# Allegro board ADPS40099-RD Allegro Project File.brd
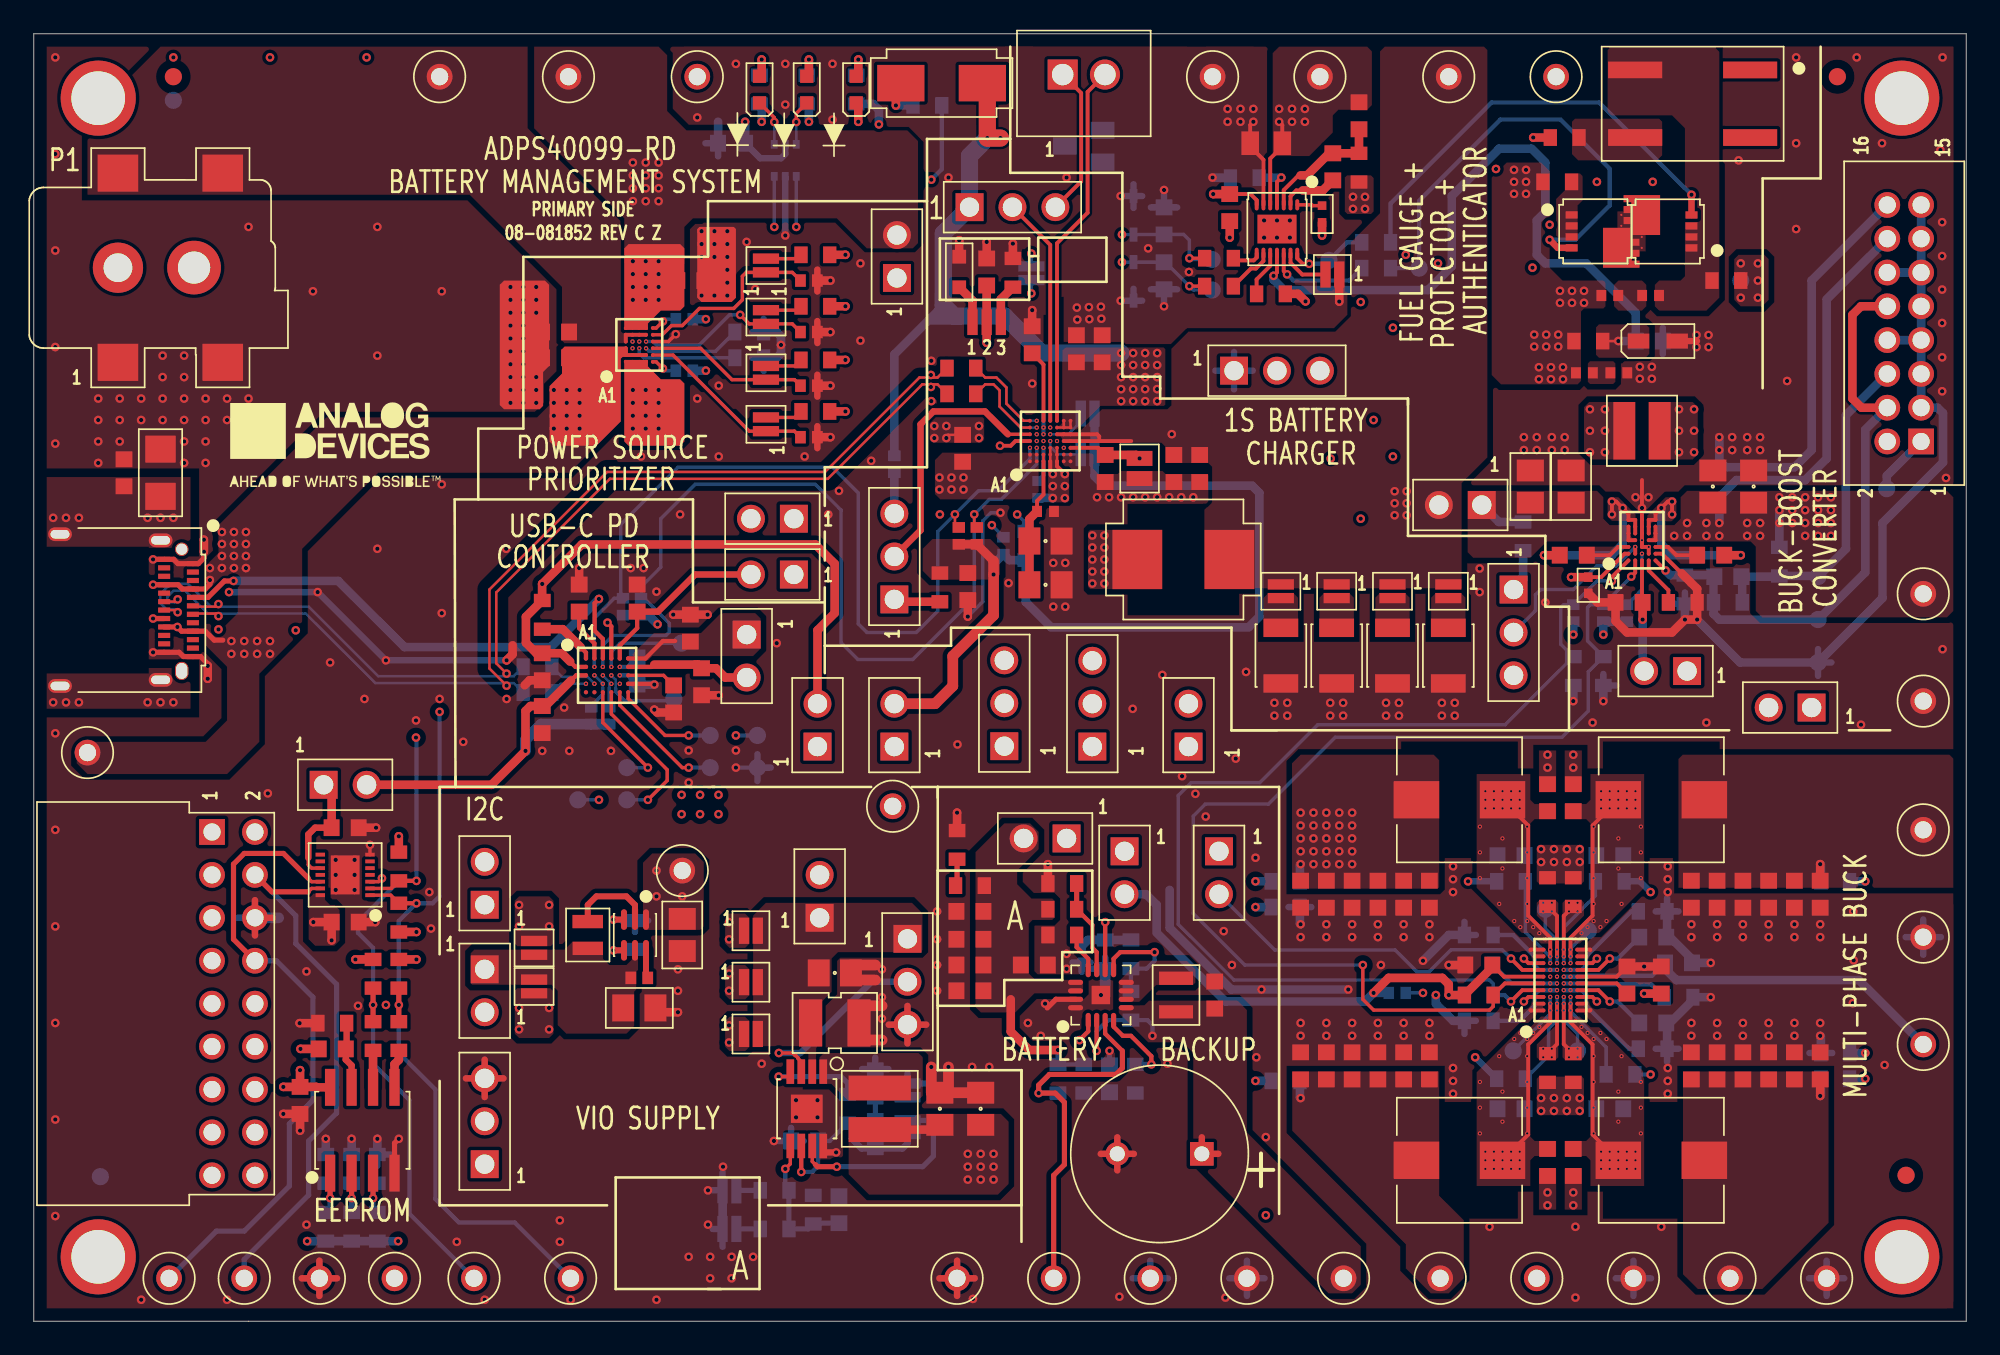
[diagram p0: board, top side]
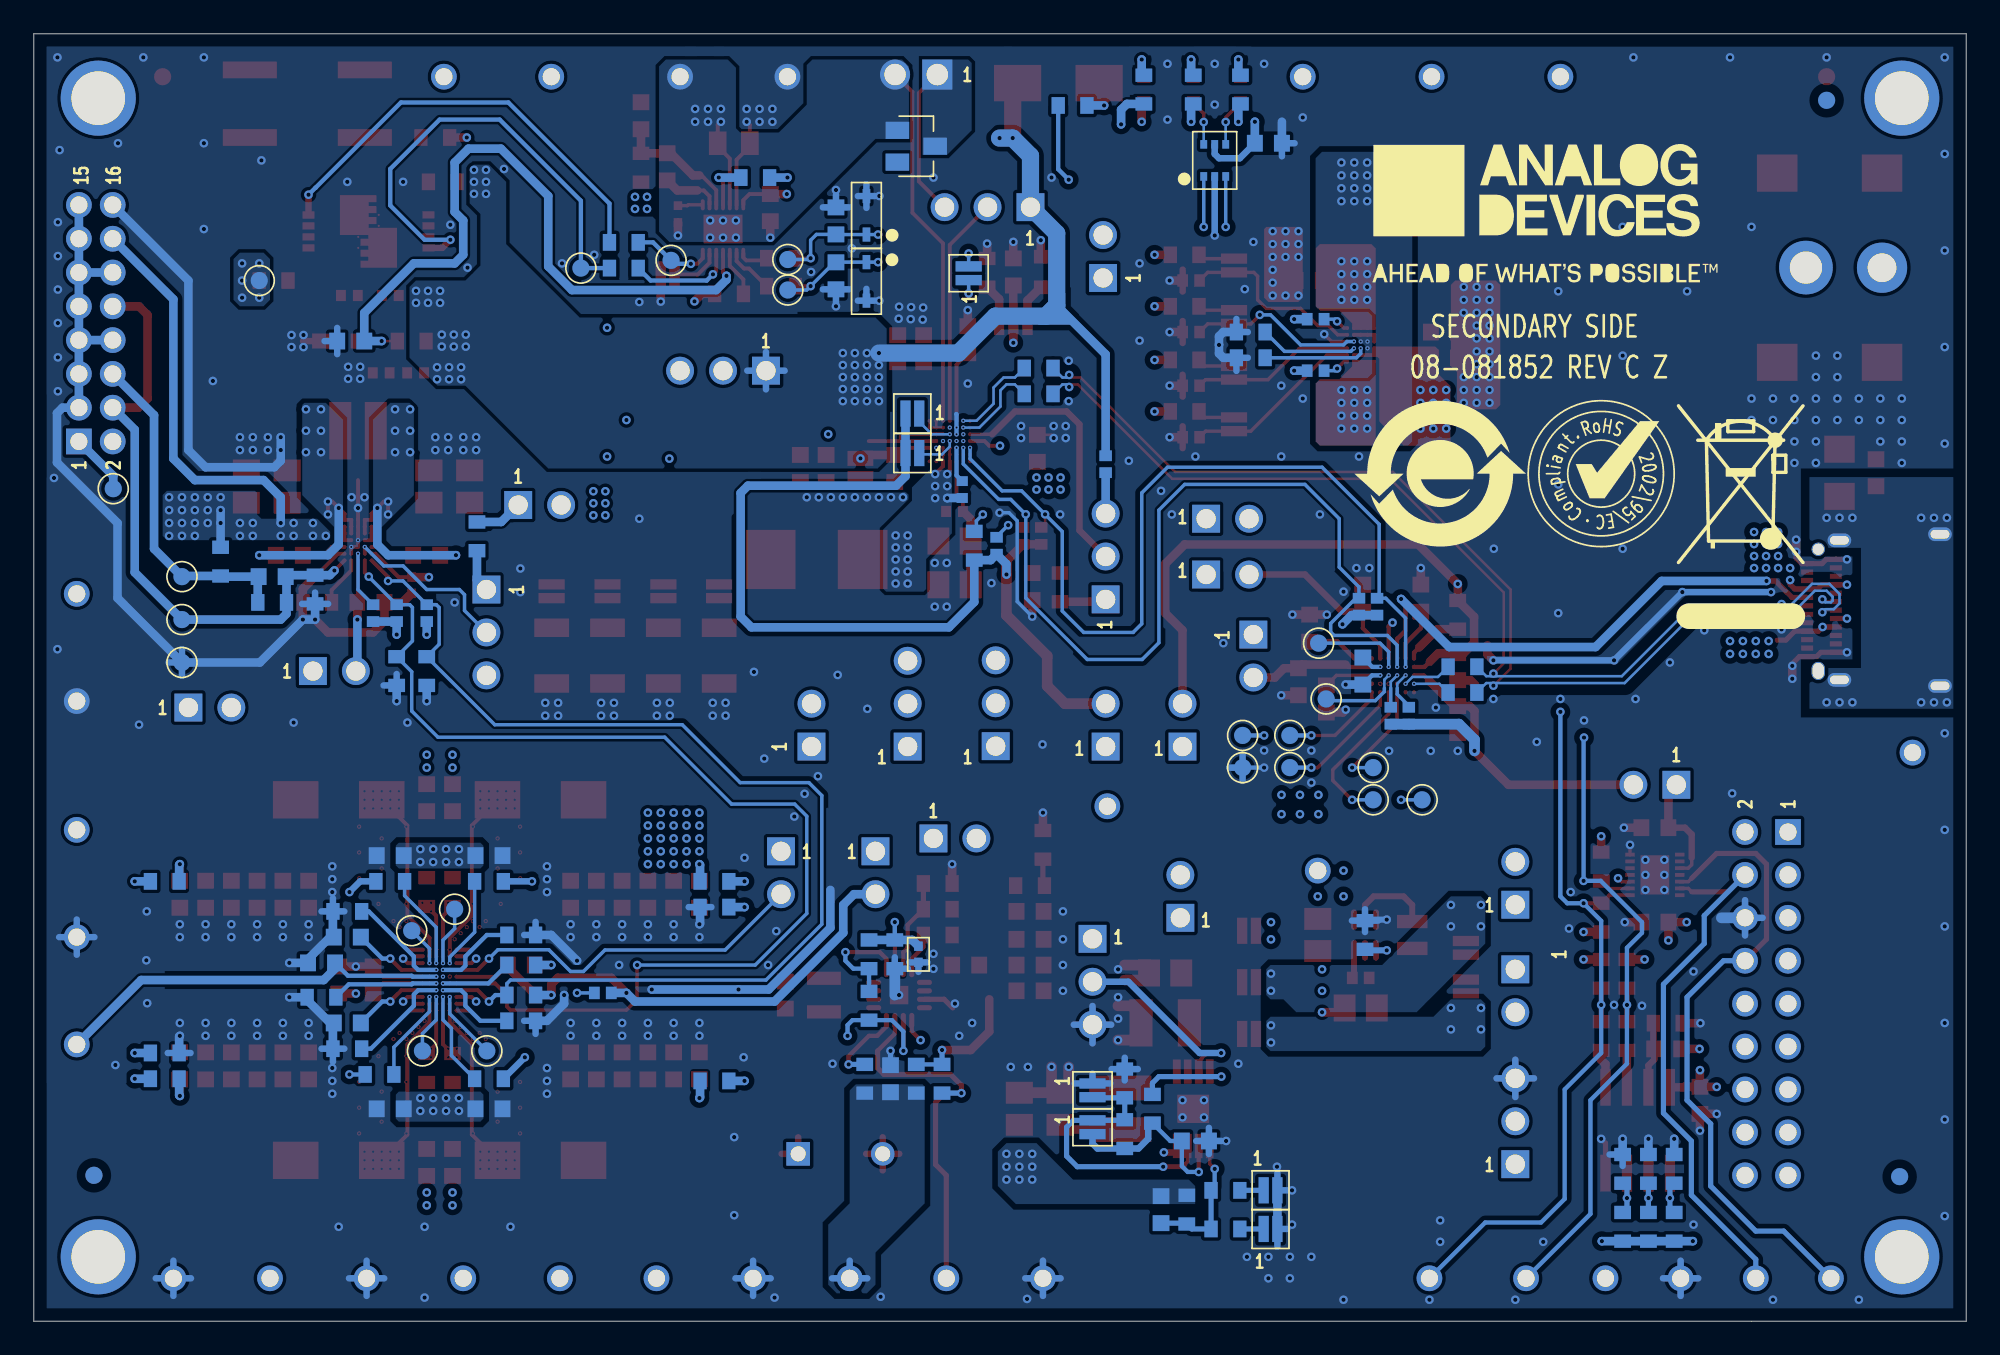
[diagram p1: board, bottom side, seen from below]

Outline 114.3 x 76.2 mm; copper layers: TOP, L2_GND, L3_SIG, L4_PWR, L5_GND, BOTTOM. Coordinates in mm from the lower left corner of the outline.
Outline path: 0,76.2 114.3,76.2 114.3,0 0,0 0,76.2

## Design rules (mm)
constraint set DEFAULT: min track width 0.152
net group USB2-IC: nets DN DP
net group USB-CN: nets DN_USBC DP_USBC
net group USB-IC1: nets DN1 DP2
net group USB_ADMAX7778X_R1: nets UNNAMED_2_ADMAX7778X_I78_DN1 UNNAMED_2_ADMAX7778X_I78_DP1
net group USB_ADMAX7778X_R2: nets UNNAMED_2_ADMAX7778X_I78_DN UNNAMED_2_ADMAX7778X_I78_DP

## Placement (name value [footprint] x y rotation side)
ALT_IN  RED  [CNKEY5001TP]  111.76 16.38 0 top
BKB  WHT  [CNKEY5001TP]  66.04 2.54 0 top
C1  0.1uF  [C0603]  5.33 50.22 270 top
C2  0.1uF  [C0603]  30.86 57.02 180 top
C3  0.1uF  [C0603]  30.86 58.55 180 top
C4  1uF  [C0603]  38.84 41.02 90 top
C5  1uF  [C0603]  30.07 38.73 270 top
C6  1uF  [C0603]  30.07 35.61 270 top
C7  1uF  [C0603]  38.86 61.59 0 top
C8  1uF  [C0603]  35.69 42.8 90 top
C9  1uF  [C0603]  35.69 38.48 270 bottom
C10  1uF  [C0603]  32.26 42.8 90 top
C11  2.2uF  [C0603]  37.85 36.83 270 top
C12  0.1uF  [C0402]  95.63 60.71 180 top
C13  1uF  [C0603]  41.28 69.72 180 bottom
C14  2.2uF  [C0603]  54.94 51.66 90 top
C15  1uF  [C0603]  55.25 43.48 270 top
C16  0.01UF  [C0603]  56.36 62.1 90 top
C17  0.22uF  [C0603]  91.06 45.34 0 top
C18  2.2uF  [C0603]  94.36 42.55 180 top
C19  1uF  [C0603]  59.05 58.09 90 top
C20  0.1uF  [C0402]  59.39 49.23 270 bottom
C21  0.22uF  [C0603]  99.19 45.34 0 top
C22  22UF  [C0603]  63.2 57.56 90 top
C23  1uF  [C0603]  63.37 50.47 270 top
C24  22uF  [C0805H60]  99.31 49.4 90 top
C25  22uF  [C0805H60]  59.84 46.18 0 top
C26  22UF  [C0603]  61.67 57.56 90 top
C27  22uF  [C0805H60]  101.73 49.4 90 top
C28  22uF  [C0805H60]  59.84 43.59 0 top
C29  0.1uF  [C0402]  59.84 47.93 0 top
C30  22UF  [C0603]  67.44 50.47 270 top
C31  22UF  [C0603]  68.96 50.47 270 top
C32  2.2uF  [C0603]  97.28 21.21 0 bottom
C33  10uF  [C0603]  87.38 12.57 180 bottom
C34  10uF  [C0603]  87.38 27.56 180 bottom
C35  10uF  [C0603]  93.22 12.57 0 bottom
C36  10uF  [C0603]  93.22 27.56 0 bottom
C37  2.2uF  [C0603]  96.27 20.19 90 top
C38  1uF  [C0603]  94.23 20.19 90 top
C39  0.1uF  [C0603]  76.84 68.33 90 top
C40  0.1uF  [C0603]  78.38 71.35 90 top
C41  0.47uF  [C0603]  70.74 65.91 270 top
C42  0.1uF  [C0603]  91.06 9.4 90 top
C43  2.2uF  [C0603]  95.76 22.73 0 bottom
C44  0.1uF  [C0603]  89.53 9.4 90 top
C45  0.1uF  [C0603]  89.53 30.99 270 top
C46  2.2uF  [C0603]  95.76 17.65 0 bottom
C47  0.1uF  [C0603]  91.06 30.99 270 top
C48  0.1uF  [C0603]  95.55 58.01 0 bottom
C49  22UF  [C0603]  98.04 15.11 90 top
C50  22UF  [C0603]  82.55 15.11 90 top
C51  22UF  [C0603]  82.55 25.27 270 top
C52  22UF  [C0603]  98.04 25.27 270 top
C53  22UF  [C0603]  99.57 15.11 90 top
C54  22UF  [C0603]  81.03 15.11 90 top
C55  22UF  [C0603]  81.03 25.27 270 top
C56  22UF  [C0603]  99.57 25.27 270 top
C57  22UF  [C0603]  101.09 15.11 90 top
C58  22UF  [C0603]  79.5 15.11 90 top
C59  22UF  [C0603]  79.5 25.27 270 top
C60  22UF  [C0603]  101.09 25.27 270 top
C61  22UF  [C0603]  102.62 15.11 90 top
C62  22UF  [C0603]  77.98 15.11 90 top
C63  22UF  [C0603]  77.98 25.27 270 top
C64  22UF  [C0603]  102.62 25.27 270 top
C65  22UF  [C0603]  104.14 15.11 90 top
C66  22UF  [C0603]  76.45 15.11 90 top
C67  22UF  [C0603]  76.45 25.27 270 top
C68  22UF  [C0603]  104.14 25.27 270 top
C69  22UF  [C0603]  105.66 15.11 90 top
C70  22UF  [C0603]  74.93 15.11 90 top
C71  22UF  [C0603]  74.93 25.27 270 top
C72  22UF  [C0603]  105.66 25.27 270 top
C73  10F  [CPLRAD197D394H472LD24]  69.09 9.91 180 top
C74  22UF  [C0603]  69.85 19.3 90 top
C75  1uF  [C0603]  85.47 21.08 180 top
C76  2200pF  [C0603]  63.63 14.35 90 bottom
C77  0.1uF  [C0402]  93.22 60.71 180 top
C78  100uF  [C1210H106]  77.06 39.4 270 top
C79  100uF  [C1210H106]  73.76 39.4 270 top
C80  100uF  [C1210H106]  83.67 39.4 270 top
C81  100uF  [C1210H106]  80.37 39.4 270 top
C82  0.1uF  [C0402]  91.72 56.13 0 top
C83  0.1uF  [C0402]  93.75 56.13 0 top
C84  10uF  [C0805H53]  88.52 49.4 90 top
C85  10uF  [C0805H53]  90.93 49.4 90 top
C86  0.47uF  [C0402H22]  91.95 43.56 270 top
C87  10pF  [C0603]  100.2 44.07 180 bottom
C88  0.47uF  [C0402H22]  61.98 21.72 270 bottom
C89  4.7uF  [C0805H60]  47.38 20.61 0 top
C90  3.3UF  [C1210H110]  47.38 17.66 0 top
C91  47uF  [C0603]  55.37 19.56 180 top
C92  47uF  [C0603]  55.37 21.08 180 top
C93  1000pF  [C0603]  66.85 65.13 90 bottom
C94  1000pF  [C0603]  66.85 61.87 270 bottom
C95  10uF  [C0805H53]  35.81 18.54 0 top
C97  22UF  [C0603]  55.37 22.61 180 top
C98  22UF  [C0603]  59.18 21.08 0 top
C101  0.1uF  [C0603]  18.41 29.21 0 top
C102  0.1uF  [C0603]  18.41 23.62 0 top
C103  1uF  [C0603]  39.5 37.85 270 top
C104  0.1uF  [C0306]  65.41 50.47 270 top
C105  1uF  [C0603]  55.37 24.26 180 top
C106  1uF  [C0603]  45.59 10.67 180 bottom
C107  22pF  [C0603]  47.62 6.6 270 bottom
C108  22uF  [C0805H60]  53.59 12.57 90 top
C109  22uF  [C0805H60]  56.01 12.57 90 top
C114  10uF  [C0805H53]  38.35 22.86 270 top
C116  0.1uF  [C0603]  15.75 13.07 270 top
C117  0.1uF  [C0603]  17.65 16.12 0 top
CSN  WHT  [CNKEY5001TP]  69.72 73.66 0 top
CSP  WHT  [CNKEY5001TP]  76.07 73.66 0 top
D1  BZX84-A5V6,215  [SOT23]  62.1 69.55 270 bottom
D2  ZLLS400TA  [SOD323]  96.06 58.01 0 top
D3  BZX84J-B5V6,115  [SOD323F]  65.05 65.46 90 bottom
D4  BZX84J-B5V6,115  [SOD323F]  65.05 61.54 270 bottom
DS1  HSMS-C191  [LED0603-2]  45.72 72.9 90 top
DS2  HSMS-C191  [LED0603-2]  42.93 72.9 90 top
DS3  HSMS-C191  [LED0603-2]  48.64 72.9 90 top
E1  120OHM  [L1206-3]  7.49 50.22 90 top
GND1  BLK  [CNKEY5001TP]  106.05 2.54 0 top
GND2  BLK  [CNKEY5001TP]  94.62 2.54 0 top
GND3  BLK  [CNKEY5001TP]  71.75 2.54 0 top
GND4  BLK  [CNKEY5001TP]  111.76 22.73 0 top
GND5  BLK  [CNKEY5001TP]  111.76 36.7 0 top
GND6  BLK  [CNKEY5001TP]  16.89 2.54 0 top
GNDC  BLK  [CNKEY5001TP]  54.61 2.54 0 top
IN+  TESTPAD  [TPSMC40]  105.54 41.53 180 bottom
IN_U3  RED  [CNKEY5001TP]  90.04 73.66 0 top
JP1  3PIN_SOLDER_JUMPER  [JPRSLD03]  56.36 59.13 0 top
L1  1.5UH  [LSMSQ118H47_WE]  95.12 52.71 180 top
L2  1UH  [LSMSQ260H118]  68 45.09 0 top
L3  1.5UH  [LSMSQ272H157]  96.27 9.53 0 top
L4  1.5UH  [LSMSQ272H157]  84.33 9.53 180 top
L5  1.5UH  [LSMSQ272H157]  84.33 30.86 180 top
L6  1.5UH  [LSMSQ272H157]  96.27 30.86 0 top
L7  0.47UH  [L1008H47]  67.56 19.3 90 top
L8  4.7uH  [LSMSQ157H83]  50.04 12.57 270 top
L9  2.2UH  [L0806_DFE]  32.77 22.86 90 top
M1  12401598E4#2A  [M12401598E4_2A]  4.41 42.09 270 top
NOREF  -  []  114.3 0 90 top
NOREF#2  -  []  0 0 0 top
NOREF#3  -  [unnamed#2]  110.49 72.39 0 top
NOREF#4  -  []  110.49 3.81 0 top
NOREF#5  -  []  0 76.2 0 top
NOREF#6  -  []  0 76.2 270 top
NOREF#7  -  []  3.81 3.81 0 top
NOREF#8  -  []  17.53 51.84 0 top
NOREF#9  -  []  114.3 0 90 top
NOREF#10  -  []  114.3 76.2 180 top
NOREF#11  -  [unnamed#2]  8.26 73.66 0 top
NOREF#12  -  []  3.81 3.81 0 top
NOREF#13  -  [unnamed#2]  3.81 72.39 0 top
NOREF#14  -  []  0 76.2 0 top
NOREF#15  -  []  193.8 133.99 0 top
NOREF#16  -  [unnamed#2]  3.81 3.81 0 top
NOREF#17  -  []  -209.55 -146.05 0 top
NOREF#18  -  [unnamed#2]  110.49 3.81 0 top
NOREF#19  -  []  0 0 0 top
NOREF#20  -  [unnamed#2]  106.68 73.66 90 top
NOREF#21  -  []  -209.55 -146.05 0 top
NOREF#22  -  []  -209.55 -146.05 0 top
NOREF#23  -  []  114.3 0 0 top
NOREF#24  -  []  171.45 307.59 0 top
NOREF#25  -  []  0 0 0 top
NOREF#26  -  [unnamed#2]  110.74 8.64 0 top
NOREF#27  -  []  56.87 95.63 0 top
NOREF#28  -  [unnamed#2]  8.26 72.26 180 bottom
NOREF#29  -  []  25.48 65.56 180 bottom
NOREF#30  -  []  31.11 50.16 180 bottom
NOREF#31  -  [unnamed#2]  110.74 8.64 180 bottom
NOREF#32  -  []  21.59 50.16 180 bottom
NOREF#33  -  [unnamed#2]  3.94 8.56 270 bottom
NOREF#34  -  []  4.06 57.86 180 bottom
OUT1  RED  [CNKEY5001TP]  100.33 2.54 0 top
OUT2  RED  [CNKEY5001TP]  83.19 2.54 0 top
OUT3  RED  [CNKEY5001TP]  88.9 2.54 0 top
OUT4  RED  [CNKEY5001TP]  111.76 29.08 180 top
OUT5  RED  [CNKEY5001TP]  111.76 43.05 0 top
OUT+  TESTPAD  [TPSMC40]  105.54 44.07 180 bottom
OUT-  TESTPAD  [TPSMC40]  105.54 38.99 180 bottom
P1  KLDX-SMT2-0202-ATR-1  [CNKYCONKLDX-SMT2-0202-ATR-1]  7.24 62.36 0 top
P2  B2B-XH-A(LF)(SN)  [CNHDR1X2H276]  60.86 73.79 0 top
P3  HTSW-102-07-T-S  [CNTHMHDR1X2L200W98H343]  70.1 27.81 270 top
P4  HTSW-102-07-T-S  [CNTHMHDR1X2L200W98H343]  105.16 36.32 180 top
P5  -  [JPSLD02]  43.31 59.44 270 top
P6  -  [JPSLD02]  43.31 56.13 270 top
P7  -  [JPSLD02]  43.31 53.09 90 top
P8  -  [JPSLD02]  43.31 62.48 90 top
P9  -  [JPSLD02]  76.81 61.95 180 top
P10  HTSW-102-07-T-S  [CNTHMHDR1X2L200W98H343]  26.67 24.65 90 top
P11  HTSW-103-07-T-S  [CNTHMHDR1X3L300W98H343]  57.4 34.04 90 top
P12  HTSW-102-07-T-S  [CNTHMHDR1X2L200W98H343]  46.48 23.88 90 top
P13  HTSW-102-07-T-S  [CNTHMHDR1X2L200W98H343]  42.16 40.64 270 top
P14  087831-1620  [CNTHMHDR2X8L734W248H260]  111.63 52.07 90 top
P15  PPPC092LJBN-RC  [CNTHFHDRRA2X9L920W335H208]  10.54 28.96 270 top
P16  HTSW-103-07-T-S  [CNTHMHDR1X3L300W98H343]  50.9 42.72 90 top
P17  HTSW-103-07-T-S  [CNTHMHDR1X3L300W98H343]  87.53 43.31 270 top
P18  HTSW-102-07-T-S  [CNTHMHDR1X2L200W98H343]  97.79 38.48 180 top
P19  HTSW-102-07-T-S  [CNTHMHDR1X2L200W98H343]  61.09 28.57 180 top
P20  HTSW-103-07-T-S  [CNTHMHDR1X3L300W98H343]  55.35 65.94 0 top
P21  HTSW-102-07-T-S  [CNTHMHDR1X2L200W98H343]  44.96 47.5 180 top
P22  HTSW-102-07-T-S  [CNTHMHDR1X2L200W98H343]  46.36 34.01 90 top
P23  HTSW-102-07-T-S  [CNTHMHDR1X2L200W98H343]  17.14 31.75 0 top
P24  HTSW-102-07-T-S  [CNTHMHDR1X2L200W98H343]  68.3 34.01 90 top
P25  -  [JPSLD02]  62.33 51.38 0 bottom
P26  HTSW-102-07-T-S  [CNTHMHDR1X2L200W98H343]  50.9 34.01 90 top
P27  HTSW-103-07-T-S  [CNTHMHDR1X3L300W98H343]  62.61 34.01 90 top
P28  -  [JPSLD02]  41.15 5.46 180 bottom
P29  HTSW-102-07-T-S  [CNTHMHDR1X2L200W98H343]  64.52 27.81 270 top
P30  HTSW-102-07-T-S  [CNTHMHDR1X2L200W98H343]  51.05 61.75 90 top
P31  -  [JPSLD02]  77.06 43.21 270 top
P32  -  [JPSLD02]  73.76 43.21 270 top
P33  -  [JPSLD02]  83.67 43.21 270 top
P34  -  [JPSLD02]  80.37 43.21 270 top
P35  HTSW-102-07-T-S  [CNTHMHDR1X2L200W98H343]  85.65 48.31 180 top
P36  -  [JPSLD02]  62.33 53.72 0 bottom
P37  -  [JPSLD02]  59 62.03 90 bottom
P38  -  [JPSLD02]  41.15 7.75 180 bottom
P39  HTSW-103-07-T-S  [CNTHMHDR1X3L300W98H343]  51.68 22.63 270 top
P40  HTSW-103-07-T-S  [CNTHMHDR1X3L300W98H343]  70.99 56.26 0 top
P41  -  [JPSLD02]  51.68 11.48 270 bottom
P42  -  [JPSLD02]  51.68 13.67 270 bottom
P43  -  [JPSLD02]  42.42 17 0 top
P44  -  [JPSLD02]  42.42 20.07 0 top
P45  -  [JPSLD02]  42.42 23.11 0 top
P46  HTSW-102-07-T-S  [CNTHMHDR1X2L200W98H343]  26.67 20.83 270 top
P47  HTSW-103-07-T-S  [CNTHMHDR1X3L300W98H343]  26.67 9.29 90 top
P48  -  [JPSLD02]  29.59 19.81 90 top
P49  -  [JPSLD02]  29.59 22.1 270 top
P50  HTSW-102-07-T-S  [CNTHMHDR1X2L200W98H343]  44.96 44.2 180 top
PP_OUT  RED  [CNKEY5001TP]  31.62 73.66 180 top
Q1  FDMC0310AS-F127  [DFN8_3_3X3_3_511DH]  96.65 64.5 90 top
Q2  FDMC0310AS-F127  [DFN8_3_3X3_3_511DH]  92.36 64.51 270 top
R1  0  [R0603]  42.32 57.02 0 bottom
R2  0  [R0603]  42.32 58.55 0 bottom
R3  1K  [R0603]  46.23 60.07 180 top
R4  1K  [R0603]  46.23 56.9 180 top
R5  2.2K  [R0402]  34.04 35.84 90 bottom
R6  100K  [R0402]  45.85 58.55 180 top
R7  100K  [R0402]  45.85 55.37 180 top
R8  2.2K  [R0402]  32.97 35.84 90 bottom
R9  100K  [R0402]  38.48 56.26 0 bottom
R10  100K  [R0402]  38.48 59.31 0 bottom
R11  100K  [R0402]  45.85 52.32 0 top
R12  100K  [R0402]  45.85 61.59 0 top
R13  1K  [R0603]  46.23 53.85 0 top
R14  1K  [R0603]  46.23 63.12 0 top
R15  10K  [R0603]  93.85 14.61 0 bottom
R16  0  [R0603]  29.79 37.21 0 bottom
R17  0  [R0603]  29.79 38.73 0 bottom
R18  150  [R0603]  45.72 72.9 90 bottom
R19  150  [R0603]  42.93 72.9 90 bottom
R20  10K  [R0603]  57.91 62.05 90 top
R21  2.2K  [R0402]  55.78 46.48 90 top
R22  2.2K  [R0402]  54.71 46.48 90 top
R23  1K  [R0603]  52.86 71.96 0 bottom
R24  0  [R0603]  58.67 45.9 270 bottom
R25  2.2K  [R0402]  34.85 42.29 90 bottom
R26  0  [R0603]  54.86 54.89 0 top
R27  15K  [R0402]  94.23 41.91 90 bottom
R28  100K  [R0402]  57.35 45.9 90 bottom
R29  150  [R0603]  48.64 72.9 90 bottom
R30  10  [R0603]  78.38 68.28 90 top
R31  10K  [R0402H26]  76.2 65.53 90 top
R32  0  [R0603]  71.63 67.69 180 bottom
R33  0.01  [R0805]  72.9 69.72 180 top
R34  200  [R0603]  73.18 60.81 0 top
R35  1K  [R0603]  79.4 63.86 0 bottom
R36  1K  [R0603]  79.4 62.33 0 bottom
R37  0  [R0603]  70.1 61.26 0 top
R38  0  [R0603]  106.55 14.35 0 bottom
R39  0  [R0603]  106.55 15.88 0 bottom
R40  0  [R0603]  74.04 14.22 180 bottom
R41  0  [R0603]  74.04 26.04 180 bottom
R42  0  [R0603]  74.04 24.51 180 bottom
R43  0  [R0603]  106.55 26.04 0 bottom
R44  0  [R0603]  100.12 61.59 0 top
R45  0  [R0603]  35.56 22.86 90 bottom
R46  64.9K  [R0603]  95.76 16.13 0 bottom
R47  10K  [R0603]  87.38 14.35 180 bottom
R48  30.9K  [R0603]  85.47 17.78 180 bottom
R49  0  [R0603]  97.28 19.18 180 bottom
R50  8.06K  [R0603]  85.47 22.86 180 bottom
R51  1.8MEG  [R0603]  64.9 18.67 90 bottom
R52  402K  [R0603]  64.9 21.72 90 bottom
R53  499K  [R0603]  63.37 21.72 270 bottom
R54  0  [R0603]  85.47 21.08 0 bottom
R55  1.62K  [R0603]  95.76 24.26 0 bottom
R56  1.5K  [R0603]  85.47 19.3 0 bottom
R57  33K  [R0603]  60.83 22.86 180 top
R58  2.2K  [R0402]  35.92 42.29 90 bottom
R59  1.5K  [R0603]  85.47 19.3 180 top
R60  100K  [R0402]  80.64 19.43 180 bottom
R61  0  [R0603]  20.32 5.59 90 bottom
R62  100K  [R0603]  20.32 9.02 90 bottom
R63  200K  [R0603]  30.07 41.81 90 top
R64  4.7K  [R0603]  53.59 43.43 270 top
R65  100K  [R0402]  50.9 50.72 270 bottom
R66  1K  [R0603]  90.55 70.06 180 top
R67  1K  [R0603]  91.95 58.01 0 top
R68  0  [R0603]  91.06 14.99 270 top
R69  0  [R0603]  55.37 25.78 180 top
R70  10K  [R0603]  87.38 26.04 180 bottom
R71  1.8MEG  [R0603]  60.83 24.38 0 top
R72  1.21M  [R0603]  60.83 25.91 180 top
R73  0  [R0603]  89.53 14.99 270 top
R74  0  [R0603]  89.53 25.4 90 top
R75  0  [R0603]  91.06 25.4 90 top
R76  510K  [R0603]  88.09 46.46 270 bottom
R77  0  [R0603]  97.54 42.55 0 top
R78  2.2K  [R0402]  91.06 41.91 90 bottom
R79  0  [R0603]  91.06 38.48 270 bottom
R80  2.2K  [R0402]  92.84 41.91 90 bottom
R81  0  [R0603]  92.84 38.48 270 bottom
R82  0  [R0603]  103.25 44.96 90 bottom
R83  0  [R0603]  100.2 42.55 180 bottom
R84  20K  [R0603]  97.66 43.31 270 bottom
R85  10K  [R0603]  93.22 26.04 0 bottom
R86  0  [R0603]  70.1 62.92 0 top
R87  0  [R0603]  90.11 67.44 0 top
R88  2.2K  [R0603]  21.59 26.91 270 top
R89  2.2K  [R0603]  21.59 23.89 90 top
R90  0  [R0603]  54.86 56.41 0 top
R91  309K  [R0603]  43.82 5.46 180 bottom
R92  84.5K  [R0603]  43.82 7.75 180 bottom
R93  0  [R0603]  54.86 54.89 180 bottom
R94  0  [R0603]  54.86 56.41 180 bottom
R95  20K  [R0603]  65.15 14.35 270 bottom
R96  1MEG  [R0603]  62.1 14.35 270 bottom
R97  1MEG  [R0603]  60.58 14.35 270 bottom
R98  100  [R0603]  54.61 28.19 90 top
R99  100K  [R0603]  48.13 12.57 270 bottom
R100  100K  [R0603]  49.77 11.07 90 bottom
R101  100K  [R0603]  49.77 14.07 90 bottom
R102  619K  [R0603]  46.1 6.6 270 bottom
R103  33M  [R0402]  35.81 20.32 0 top
R109  100K  [R0603]  18.8 5.59 90 bottom
R110  0  [R0603]  18.8 9.02 90 bottom
R111  0  [R0603]  17.27 5.59 90 bottom
R112  100K  [R0603]  17.27 9.02 90 bottom
R113  0  [R0603]  20.07 16.88 90 top
R114  0  [R0603]  21.59 16.88 90 top
R115  10K  [R0603]  20.07 20.56 270 top
R116  10K  [R0603]  21.59 20.56 270 top
R117  0  [R0603]  17.65 17.64 180 top
RDY  WHT  [CNKEY5001TP]  60.33 2.54 0 top
RT1  10K  [R0603H35]  54.74 62.1 90 top
S1  EVQ-Q2K03W  [SWPANASONIC_EVQ]  98.12 72.06 180 top
S2  TL3302AF130QJ  [SWSML236W138H205]  53.7 73.28 0 top
SCL  WHT  [CNKEY5001TP]  26.04 2.54 0 top
SCL_EXT  WHT  [CNKEY5001TP]  8 2.54 0 top
SDA  WHT  [CNKEY5001TP]  31.75 2.54 0 top
SDA_EXT  WHT  [CNKEY5001TP]  12.45 2.54 0 top
TP1  TESTPAD  [TPSMC40]  40.01 34.67 180 bottom
TP6  TESTPAD  [TPSMC40]  76.61 62.79 180 bottom
TP9  TESTPAD  [TPSMC40]  38.3 40.13 180 bottom
TP10  TESTPAD  [TPSMC40]  40.01 32.77 180 bottom
TP11  TESTPAD  [TPSMC40]  42.8 34.67 180 bottom
TP12  TESTPAD  [TPSMC40]  35.08 30.86 180 bottom
TP13  TESTPAD  [TPSMC40]  35.08 32.77 180 bottom
TP17  TESTPAD  [TPSMC40]  32.18 30.86 180 bottom
TP18  TESTPAD  [TPSMC40]  37.86 36.83 180 bottom
TP19  TESTPAD  [TPSMC40]  42.8 32.77 180 bottom
TP20  TESTPAD  [TPSMC40]  69.7 62.84 180 bottom
TP21  TESTPAD  [TPSMC40]  109.6 49.28 180 bottom
TP23  TESTPAD  [TPSMC40]  91.31 16 180 bottom
TP25  TESTPAD  [TPSMC40]  87.5 16 180 bottom
TP27  TESTPAD  [TPSMC40]  89.41 24.38 180 bottom
TP29  TESTPAD  [TPSMC40]  91.95 23.11 180 bottom
TP30  TESTPAD  [TPSMC40]  100.97 61.59 180 bottom
TP31  TESTPAD  [TPSMC40]  69.7 61.04 180 bottom
TP32  TESTPAD  [TPSMC40]  81.94 62.33 180 bottom
U1  MAX14727EWV+  [WLP30_21-0762]  35.81 57.79 90 top
U2  MAX77958EWV+  [WLCSP30H27]  33.91 38.23 270 top
U3  MAX77857BEWB+  [WLCSP35H27]  95.12 46.23 0 top
U4  MAX17300G+  [DFN14_3X3_PAD2_3X1_7]  73.53 64.64 180 top
U5  MAX38889AATE+  [QFN16_3X3_PAD1_1X1_1]  63.12 19.3 0 top
U6  MAX77542BAWU+T  [WLCSP60H27]  90.3 20.19 0 top
U7  NC7WZ07P6X  [SC70]  44.45 68.71 180 bottom
U8  MAX77786EWJ+  [WLP49_2_958X2_958]  60.12 52.1 90 top
U9  LTC3621IMS8E#PBF  [MSOP8_PAD1_88X1_68]  45.72 12.57 180 top
U10  MAX17224ALT+  [DFN6_2X2]  35.56 22.86 180 top
U13  MAX14611ETD+  [TDFN14_PAD2_3X1_7]  18.41 26.42 90 top
U14  24AA32A-I/SN  [SO8]  19.43 11.3 0 top
UNK1V8_VIO  RED  [CNKEY5001TP]  50.8 30.48 0 top
UNK5V0_VIO  RED  [CNKEY5001TP]  38.35 26.67 0 top
UNK12V0  RED  [CNKEY5001TP]  24 73.66 0 top
VBUS  RED  [CNKEY5001TP]  3.17 33.66 0 top
VCAP  RED  [CNKEY5001TP]  77.47 2.54 0 top
VCC_EXT  RED  [CNKEY5001TP]  21.34 2.54 0 top
VIO  RED  [CNKEY5001TP]  39.24 73.66 180 top
VSYS  RED  [CNKEY5001TP]  83.69 73.66 0 top

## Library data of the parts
ALT_IN IN_U3 OUT1-OUT5 PP_OUT UNK1V8_VIO UNK5V0_VIO UNK12V0 VBUS VCAP VCC_EXT VIO VSYS = CNTP1P: Tolerance: N/A; User Part Number: UPN; alternate symbols: (CNKEY5001TP); part number: CNTP1P_TH-RED,E016323,CNKEY5001TP; tolerance: N/A
BKB CSN CSP RDY SCL SCL_EXT SDA SDA_EXT = CNTP1P: Tolerance: N/A; User Part Number: UPN; alternate symbols: (CNKEY5001TP); part number: CNTP1P_TH-WHT,E006153,CNKEY5001TP; tolerance: N/A
C1-C3 C39 C40 C42 C44 C45 C47 C48 C101 C102 C116 C117 = CAP: User Part Number: UPN; Tolerance: 10; alternate symbols: (C0603); part number: CAP_SM-0.1UF,25V,10,E013746,C0603; tolerance: 10
C4-C10 C13 C15 C19 C23 C38 C75 C103 C105 C106 = CAP: User Part Number: UPN; Tolerance: 10; alternate symbols: (C0603); part number: CAP_SM-1UF,50V,10,E032711,C0603; tolerance: 10
C11 C14 C18 C32 C37 C43 C46 = CAP: User Part Number: UPN; Tolerance: 10; alternate symbols: (C0603); part number: CAP_SM-2.2UF,25V,10,E031885,C0603; tolerance: 10
C12 C77 C82 C83 = CAP: User Part Number: UPN; Tolerance: 10; alternate symbols: (C0402); part number: CAP_SM-0.1UF,25V,10,E025798,C0402; tolerance: 10
C16 = CAP: User Part Number: UPN; Tolerance: 5; alternate symbols: (C0603); part number: CAP_SM-0.01UF,50V,5,E054559,C0603; tolerance: 5
C17 C21 = CAP: User Part Number: UPN; Tolerance: 10; alternate symbols: (C0603); part number: CAP_SM-0.22UF,50V,10,E015565,C0603; tolerance: 10
C20 C29 = CAP: User Part Number: UPN; Tolerance: 10; alternate symbols: (C0402); part number: CAP_SM-0.1UF,50V,10,E028943,C0402; tolerance: 10
C22 C26 C30 C31 C49-C72 C74 C97 C98 = CAP: User Part Number: UPN; Tolerance: 20; alternate symbols: (C0603); part number: CAP_SM-22UF,10V,20,E059718,C0603; tolerance: 20
C24 C25 C27 C28 C108 C109 = CAP: Tolerance: 20; User Part Number: UPN; alternate symbols: (C0805H60); part number: CAP_SM-22UF,35V,20,E025497,C0805H60; tolerance: 20
C33-C36 = CAP: User Part Number: UPN; Tolerance: 10; alternate symbols: (C0603); part number: CAP_SM-10UF,10V,10,E020723,C0603; tolerance: 10
C41 = CAP: User Part Number: UPN; Tolerance: 10; alternate symbols: (C0603); part number: CAP_SM-0.47UF,35V,10,E019601,C0603; tolerance: 10
C73 = CAPP: User Part Number: UPN; Tolerance: -10%,+30; alternate symbols: (CPLRAD197D394H472LD24); part number: CAPP_TH-10F,3V,-10%,+30,E065865,CPLRAD197D394H472LD24; tolerance: -10%,+30
C76 = CAP: User Part Number: UPN; Tolerance: 5; alternate symbols: (C0603); part number: CAP_SM-2200PF,50V,5,E012265,C0603; tolerance: 5
C78-C81 = CAP: Tolerance: 20; User Part Number: UPN; alternate symbols: (C1210H106); part number: CAP_SM-100UF,16V,20,E029581,C1210H106; tolerance: 20
C84 C85 C95 C114 = CAP: Tolerance: 10; User Part Number: UPN; alternate symbols: (C0805H53); part number: CAP_SM-10UF,25V,10,E029697,C0805H53; tolerance: 10
C86 C88 = CAP: Tolerance: 10; User Part Number: UPN; alternate symbols: (C0402H22); part number: CAP_SM-0.47UF,6.3V,10,E030257,C0402H22; tolerance: 10
C87 = CAP: User Part Number: UPN; Tolerance: 5; alternate symbols: (C0603); part number: CAP_SM-10PF,250V,5,E017800,C0603; tolerance: 5
C89 = CAP: Tolerance: 10; User Part Number: UPN; alternate symbols: (C0805H60); part number: CAP_SM-4.7UF,25V,10,E024738,C0805H60; tolerance: 10
C90 = CAP: Tolerance: 20; User Part Number: UPN; alternate symbols: (C1210H110); part number: CAP_SM-3.3UF,50V,20,E042926,C1210H110; tolerance: 20
C91 C92 = CAP: User Part Number: UPN; Tolerance: 20; alternate symbols: (C0603); part number: CAP_SM-47UF,6.3V,20,E032368,C0603; tolerance: 20
C93 C94 = CAP: User Part Number: UPN; Tolerance: 5; alternate symbols: (C0603); part number: CAP_SM-1000PF,25V,5,E035602,C0603; tolerance: 5
C104 = CAP: Tolerance: 10; User Part Number: UPN; alternate symbols: (C0306); part number: CAP_SM-0.1UF,10V,10,E000379,C0306; tolerance: 10
C107 = CAP: User Part Number: UPN; Tolerance: 5; alternate symbols: (C0603); part number: CAP_SM-22PF,50V,5,E000411,C0603; tolerance: 5
D1 = DIOZNR3P_V3: User Part Number: UPN; Tolerance: 1; alternate symbols: (SOT23); part number: DIOZNR3P_V3_SM-BZX84-A5V6,215,5.6V,1,E045330,SOT23; tolerance: 1
D2 = DIOSCHOTTKY: Tolerance: N/A; User Part Number: UPN; alternate symbols: (SOD323); part number: DIOSCHOTTKY_SM-ZLLS400TA,40V,N/A,E032795,SOD323; tolerance: N/A
D3 D4 = DIOZNR: Tolerance: 2; User Part Number: UPN; alternate symbols: (SOD323F); part number: DIOZNR_SM-BZX84J-B5V6,115,5.6V,2,E059375,SOD323F; tolerance: 2
DS1-DS3 = DIOLED: Tolerance: N/A; User Part Number: UPN; alternate symbols: (LED0603-2); part number: DIOLED_SM-HSMS-C191,2.1V,N/A,E029018,LED0603-2; tolerance: N/A
E1 = FERRITE: Tolerance: 25; User Part Number: UPN; alternate symbols: (L1206-3); part number: FERRITE_SM-120OHM,25,E021151,L1206-3; tolerance: 25
GND1-GND6 GNDC = CNTP1P: Tolerance: N/A; User Part Number: UPN; alternate symbols: (CNKEY5001TP); part number: CNTP1P_TH-BLK,E005347,CNKEY5001TP; tolerance: N/A
IN+ OUT+ OUT- TP1 TP6 TP9-TP13 TP17-TP21 TP23 TP25 TP27 TP29-TP32 = NCTESTPAD: Tolerance: N/A; User Part Number: UPN; alternate symbols: (TPSMC40); part number: NCTESTPAD_SM-TESTPAD,E019801,TPSMC40; tolerance: N/A
JP1 = NC3P_JMPR: Tolerance: N/A; User Part Number: UPN; alternate symbols: (JPRSLD03); part number: NC3P_JMPR_SM-3PIN_SOLDER_JUMPER,E005606,JPRSLD03; tolerance: N/A
L1 = IND: User Part Number: UPN; Tolerance: 20; alternate symbols: (LSMSQ118H47_WE); part number: IND_SM-1.5UH,20,E046524,LSMSQ118H47_WE; tolerance: 20
L2 = IND: User Part Number: UPN; Tolerance: 20; alternate symbols: (LSMSQ260H118); part number: IND_SM-1UH,20,E044803,LSMSQ260H118; tolerance: 20
L3-L6 = IND: Tolerance: 20; User Part Number: UPN; alternate symbols: (LSMSQ272H157); part number: IND_SM-1.5UH,20,E028905,LSMSQ272H157; tolerance: 20
L7 = IND: Tolerance: 20; User Part Number: UPN; alternate symbols: (L1008H47); part number: IND_SM-0.47UH,20,E029341,L1008H47; tolerance: 20
L8 = IND: User Part Number: UPN; Tolerance: 20; alternate symbols: (LSMSQ157H83); part number: IND_SM-4.7UH,20,E014920,LSMSQ157H83; tolerance: 20
L9 = IND: Tolerance: 20; User Part Number: UPN; alternate symbols: (L0806_DFE); part number: IND_SM-2.2UH,20,E064504,L0806_DFE; tolerance: 20
M1 = MODUSB24P_4PSHLD: User Part Number: UPN; Tolerance: N/A; alternate symbols: (M12401598E4_2A); part number: MODUSB24P_4PSHLD_SM-12401598E4#2A,E031205,M12401598E4_2A; tolerance: N/A
P1 = CN4P_V2: User Part Number: UPN; Tolerance: N/A; alternate symbols: (CNKYCONKLDX-SMT2-0202-ATR-1); part number: CN4P_V2_SM-KLDX-SMT2-0202-ATR-1,E066193,CNKYCONKLDX-SMT2-0202-ATR-1; tolerance: N/A
P2 = CN2P: User Part Number: UPN; Tolerance: N/A; alternate symbols: (CNHDR1X2H276); part number: CN2P_TH-B2B-XH-A(LF)(SN),E021915,CNHDR1X2H276; tolerance: N/A
P3 P4 P10 P12 P13 P18 P19 P21-P24 P26 P29 P30 P35 P46 P50 = CN2P: User Part Number: UPN; Tolerance: N/A; alternate symbols: (CNTHMHDR1X2L200W98H343); part number: CN2P_TH-HTSW-102-07-T-S,E027227,CNTHMHDR1X2L200W98H343; tolerance: N/A
P5-P9 P25 P28 P31-P34 P36-P38 P41-P45 P48 P49 = NC2P: User Part Number: UPN; Tolerance: N/A; alternate symbols: (JPSLD02); part number: NC2P_SM-JPSLD02,E006230,JPSLD02; tolerance: N/A
P11 P16 P17 P20 P27 P39 P40 P47 = CN3P: User Part Number: UPN; Tolerance: N/A; alternate symbols: (CNTHMHDR1X3L300W98H343); part number: CN3P_TH-HTSW-103-07-T-S,E027228,CNTHMHDR1X3L300W98H343; tolerance: N/A
P14 = CN16P: Tolerance: N/A; User Part Number: UPN; alternate symbols: (CNTHMHDR2X8L734W248H260); part number: CN16P_TH-087831-1620,E048667,CNTHMHDR2X8L734W248H260; tolerance: N/A
P15 = CN18P: User Part Number: UPN; Tolerance: N/A; alternate symbols: (CNTHFHDRRA2X9L920W335H208); part number: CN18P_TH-PPPC092LJBN-RC,E072573,CNTHFHDRRA2X9L920W335H208; tolerance: N/A
Q1 Q2 = TRANNMOSFET_V15: Tolerance: N/A; User Part Number: UPN; alternate symbols: (DFN8_3_3X3_3_511DH); part number: TRANNMOSFET_V15_SM-FDMC0310AS-F127,E073294,DFN8_3_3X3_3_511DH; tolerance: N/A
R1 R2 R16 R17 R24 R26 R32 R37-R45 R49 R54 R61 R68 R69 R73-R75 R77 R79 R81-R83 R86 R87 R90 R93 R94 R110 R111 R113 R114 R117 = RES: User Part Number: UPN; Tolerance: JUMPER; alternate symbols: (R0603); part number: RES_SM-0,E006826,1/10W,JUMPER,R0603; tolerance: JUMPER
R3 R4 R13 R14 R23 R35 R36 R66 R67 = RES: User Part Number: UPN; Tolerance: 1; alternate symbols: (R0603); part number: RES_SM-1K,E029591,1/10W,1,R0603; tolerance: 1
R5 R8 R21 R22 R25 R58 R78 R80 = RES: User Part Number: UPN; Tolerance: 5; alternate symbols: (R0402); part number: RES_SM-2.2K,E003446,1/10W,5,R0402; tolerance: 5
R6 R7 R9-R12 R28 R60 R65 = RES: User Part Number: UPN; Tolerance: 1; alternate symbols: (R0402); part number: RES_SM-100K,E003796,1/10W,1,R0402; tolerance: 1
R15 R20 R47 R70 R85 R115 R116 = RES: User Part Number: UPN; Tolerance: 1; alternate symbols: (R0603); part number: RES_SM-10K,E003671,1/10W,1,R0603; tolerance: 1
R18 R19 R29 = RES: User Part Number: UPN; Tolerance: 1; alternate symbols: (R0603); part number: RES_SM-150,E003691,1/10W,1,R0603; tolerance: 1
R27 = RES: User Part Number: UPN; Tolerance: 1; alternate symbols: (R0402); part number: RES_SM-15K,E045854,1/16W,1,R0402; tolerance: 1
R30 = RES: User Part Number: UPN; Tolerance: 1; alternate symbols: (R0603); part number: RES_SM-10,E045254,1/33W,1,R0603; tolerance: 1
R31 = RESTHERM: Tolerance: 1; User Part Number: UPN; alternate symbols: (R0402H26); part number: RESTHERM_SM-10K,E022279,0.66W,1,R0402H26; tolerance: 1
R33 = RES: User Part Number: UPN; Tolerance: 1; alternate symbols: (R0805); part number: RES_SM-0.01,E062773,1/2W,1,R0805; tolerance: 1
R34 = RES: User Part Number: UPN; Tolerance: 1; alternate symbols: (R0603); part number: RES_SM-200,E007248,1/10W,1,R0603; tolerance: 1
R46 = RES: User Part Number: UPN; Tolerance: 1; alternate symbols: (R0603); part number: RES_SM-64.9K,E010256,1/10W,1,R0603; tolerance: 1
R48 = RES: User Part Number: UPN; Tolerance: 1; alternate symbols: (R0603); part number: RES_SM-30.9K,E021944,1/10W,1,R0603; tolerance: 1
R50 = RES: User Part Number: UPN; Tolerance: 1; alternate symbols: (R0603); part number: RES_SM-8.06K,E046150,1/10W,1,R0603; tolerance: 1
R51 R71 = RES: User Part Number: UPN; Tolerance: 1; alternate symbols: (R0603); part number: RES_SM-1.8MEG,E036004,1/10W,1,R0603; tolerance: 1
R52 = RES: User Part Number: UPN; Tolerance: 1; alternate symbols: (R0603); part number: RES_SM-402K,E026771,1/10W,1,R0603; tolerance: 1
R53 = RES: User Part Number: UPN; Tolerance: 1; alternate symbols: (R0603); part number: RES_SM-499K,E015340,1/10W,1,R0603; tolerance: 1
R55 = RES: User Part Number: UPN; Tolerance: 0.1; alternate symbols: (R0603); part number: RES_SM-1.62K,E046035,1/10W,0.1,R0603; tolerance: 0.1
R56 R59 = RES: User Part Number: UPN; Tolerance: 0.1; alternate symbols: (R0603); part number: RES_SM-1.5K,E010316,1/10W,0.1,R0603; tolerance: 0.1
R57 = RES: User Part Number: UPN; Tolerance: 1; alternate symbols: (R0603); part number: RES_SM-33K,E028267,1/10W,1,R0603; tolerance: 1
R62 R99-R101 R109 R112 = RES: User Part Number: UPN; Tolerance: 1; alternate symbols: (R0603); part number: RES_SM-100K,E030871,1/10W,1,R0603; tolerance: 1
R63 = RES: User Part Number: UPN; Tolerance: 1; alternate symbols: (R0603); part number: RES_SM-200K,E015343,1/10W,1,R0603; tolerance: 1
R64 = RES: User Part Number: UPN; Tolerance: 1; alternate symbols: (R0603); part number: RES_SM-4.7K,E017860,1/10W,1,R0603; tolerance: 1
R72 = RES: User Part Number: UPN; Tolerance: 1; alternate symbols: (R0603); part number: RES_SM-1.21M,E063409,1/10W,1,R0603; tolerance: 1
R76 = RES: User Part Number: UPN; Tolerance: 1; alternate symbols: (R0603); part number: RES_SM-510K,E026533,1/10W,1,R0603; tolerance: 1
R84 R95 = RES: User Part Number: UPN; Tolerance: 5; alternate symbols: (R0603); part number: RES_SM-20K,E003851,1/10W,5,R0603; tolerance: 5
R88 R89 = RES: User Part Number: UPN; Tolerance: 1; alternate symbols: (R0603); part number: RES_SM-2.2K,E070000,1/10W,1,R0603; tolerance: 1
R91 = RES: User Part Number: UPN; Tolerance: 0.1; alternate symbols: (R0603); part number: RES_SM-309K,E054959,1/10W,0.1,R0603; tolerance: 0.1
R92 = RES: User Part Number: UPN; Tolerance: 1; alternate symbols: (R0603); part number: RES_SM-84.5K,E069902,1/10W,1,R0603; tolerance: 1
R96 R97 = RES: User Part Number: UPN; Tolerance: 1; alternate symbols: (R0603); part number: RES_SM-1MEG,E030873,1/10W,1,R0603; tolerance: 1
R98 = RES: User Part Number: UPN; Tolerance: 1; alternate symbols: (R0603); part number: RES_SM-100,E003668,1/10W,1,R0603; tolerance: 1
R102 = RES: User Part Number: UPN; Tolerance: 1; alternate symbols: (R0603); part number: RES_SM-619K,E036091,1/10W,1,R0603; tolerance: 1
R103 = RES: User Part Number: UPN; Tolerance: 5; alternate symbols: (R0402); part number: RES_SM-33M,E075030,1/16W,5,R0402; tolerance: 5
RT1 = RESTHERM: Tolerance: 1; User Part Number: UPN; alternate symbols: (R0603H35); part number: RESTHERM_SM-10K,E025118,1/10W,1,R0603H35; tolerance: 1
S1 = SWSPST4PIN_B: Tolerance: N/A; User Part Number: UPN; alternate symbols: (SWPANASONIC_EVQ); part number: SWSPST4PIN_B_SM-EVQ-Q2K03W,E039231,SWPANASONIC_EVQ; tolerance: N/A
S2 = SWSPST2PIN_V2: User Part Number: UPN; Tolerance: N/A; alternate symbols: (SWSML236W138H205); part number: SWSPST2PIN_V2_SM-TL3302AF130QJ,E075192,SWSML236W138H205; tolerance: N/A
U1 = ADMAX147XX: User Part Number: UPN; Tolerance: N/A; alternate symbols: (WLP30_21-0762); part number: ADMAX147XX_SM-MAX14727EWV+,E064140,WLP30_21-0762; tolerance: N/A
U2 = ICMAX77958: User Part Number: UPN; Tolerance: N/A; alternate symbols: (WLCSP30H27); part number: ICMAX77958_SM-MAX77958EWV+,E045058,WLCSP30H27; tolerance: N/A
U3 = ADMAX77857: Tolerance: N/A; User Part Number: UPN; alternate symbols: (WLCSP35H27); part number: ADMAX77857_SM-MAX77857BEWB+,E056830,WLCSP35H27; tolerance: N/A
U4 = ADMAX173XX_V2: Tolerance: N/A; User Part Number: UPN; alternate symbols: (DFN14_3X3_PAD2_3X1_7); part number: ADMAX173XX_V2_SM-MAX17300G+,E066489,DFN14_3X3_PAD2_3X1_7; tolerance: N/A
U5 = ADMAX38889: User Part Number: UPN; Tolerance: N/A; alternate symbols: (QFN16_3X3_PAD1_1X1_1); part number: ADMAX38889_SM-MAX38889AATE+,E067937,QFN16_3X3_PAD1_1X1_1; tolerance: N/A
U6 = ADMAX77542: User Part Number: UPN; Tolerance: N/A; alternate symbols: (WLCSP60H27); part number: ADMAX77542_SM-MAX77542BAWU+T,E075244,WLCSP60H27; tolerance: N/A
U7 = NC7WZ07: Tolerance: N/A; User Part Number: UPN; alternate symbols: (SC70); part number: NC7WZ07_SM-NC7WZ07P6X,E006191,SC70; tolerance: N/A
U8 = ADMAX7778X: User Part Number: UPN; Tolerance: N/A; alternate symbols: (WLP49_2_958X2_958); part number: ADMAX7778X_SM-MAX77786EWJ+,E066708,WLP49_2_958X2_958; tolerance: N/A
U9 = ADLTC3621_V2: Tolerance: N/A; User Part Number: UPN; alternate symbols: (MSOP8_PAD1_88X1_68); part number: ADLTC3621_V2_SM-LTC3621IMS8E#PBF,E048090,MSOP8_PAD1_88X1_68; tolerance: N/A
U10 = ADMAX1722X: Tolerance: N/A; User Part Number: UPN; alternate symbols: (DFN6_2X2); part number: ADMAX1722X_SM-MAX17224ALT+,E058914,DFN6_2X2; tolerance: N/A
U13 = ICMAX14611: Tolerance: N/A; User Part Number: UPN; alternate symbols: (TDFN14_PAD2_3X1_7); part number: ICMAX14611_SM-MAX14611ETD+,E029251,TDFN14_PAD2_3X1_7; tolerance: N/A
U14 = IC24XX32A_V2: Tolerance: N/A; User Part Number: UPN; alternate symbols: (SO8); part number: IC24XX32A_V2_SM-24AA32A-I/SN,E034913,SO8; tolerance: N/A

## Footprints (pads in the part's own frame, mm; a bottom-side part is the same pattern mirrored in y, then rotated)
C0306
  rect 0.889x1.524 smd: 1(-0.597,0) 2(0.597,0)
C0402
  rect 0.584x0.66 smd: 1(-0.5,0) 2(0.5,0)
C0402H22
  rect 0.559x0.508 smd: 1(-0.479,0) 2(0.479,0)
C0603
  rect 0.94x0.991 smd: 1(-0.8,0) 2(0.8,0)
C0805H53
  rect 1.295x1.6 smd: 1(-0.953,0) 2(0.953,0)
C0805H60
  rect 1.295x1.6 smd: 1(-0.953,0) 2(0.953,0)
C1210H106
  rect 1.092x2.057 smd: 1(-1.646,0) 2(1.646,0)
C1210H110
  rect 1.372x2.794 smd: 1(-1.431,0) 2(1.431,0)
CNHDR1X2H276
  rect 1.778x1.778 hole 1.27: 1(0,0)
  round 1.778 hole 1.27: 2(2.5,0)
CNKEY5001TP
  round 1.524 hole 1.016: 1(0,0)
CNKYCONKLDX-SMT2-0202-ATR-1
  round 2.972 hole 1.702 unplated: (-2.262,-0.003)
  round 3.175 hole 1.905 unplated: (2.24,0.005)
  rect 2.4x2.2 smd: 1(-2.262,-5.603) 2(3.938,-5.603) 3(3.938,5.597) 4(-2.262,5.597)
CNTHFHDRRA2X9L920W335H208
  rect 1.524x1.524 hole 1.016: 1(0,0)
  round 1.524 hole 1.016: 2(0,2.54) 3(2.54,0) 4(2.54,2.54) 5(5.08,0) 6(5.08,2.54) 7(7.62,0) 8(7.62,2.54) 9(10.16,0) 10(10.16,2.54) 11(12.7,0) 12(12.7,2.54) 13(15.24,0) 14(15.24,2.54) 15(17.78,0) 16(17.78,2.54) 17(20.32,0) 18(20.32,2.54)
CNTHMHDR1X2L200W98H343
  rect 1.651x1.651 hole 1.143: 1(0,0)
  round 1.651 hole 1.143: 2(2.54,0)
CNTHMHDR1X3L300W98H343
  rect 1.651x1.651 hole 1.143: 1(0,0)
  round 1.651 hole 1.143: 2(2.54,0) 3(5.08,0)
CNTHMHDR2X8L734W248H260
  rect 1.524x1.524 hole 1.016: 1(0,0)
  round 1.524 hole 1.016: 2(0,2) 3(2,0) 4(2,2) 5(4,0) 6(4,2) 7(6,0) 8(6,2) 9(8,0) 10(8,2) 11(10,0) 12(10,2) 13(12,0) 14(12,2) 15(14,0) 16(14,2)
CPLRAD197D394H472LD24
  round 1.397 hole 0.889: N(5,0)
  rect 1.397x1.397 hole 0.889: P(0,0)
DFN6_2X2
  oval 0.356x1.219 smd: 1(-0.65,-0.91) 2(0,-0.91) 3(0.65,-0.91) 4(0.65,0.91) 5(0,0.91) 6(-0.65,0.91)
DFN8_3_3X3_3_511DH
  rect 0.432x0.711 smd: 1(-0.975,-1.405) 2(-0.325,-1.405) 3(0.325,-1.405) 4(0.975,-1.405)
  custom 0.54x0.54 smd: 5(0.97,1.532)
  round 0.127 smd: 6(0.325,1.535) 7(-0.325,1.535) 8(-0.975,1.535)
DFN14_3X3_PAD2_3X1_7
  oval 0.229x0.66 smd: 1(-1.2,-1.435) 2(-0.8,-1.435) 3(-0.4,-1.435) 4(0,-1.435) 5(0.4,-1.435) 6(0.8,-1.435) 7(1.2,-1.435) 8(1.2,1.435) 9(0.8,1.435) 10(0.4,1.435) 11(0,1.435) 12(-0.4,1.435) 13(-0.8,1.435) 14(-1.2,1.435)
  rect 2.311x1.702 smd: PAD(0,0)
JPRSLD03
  rect 0.61x1.524 smd: 1(-0.838,0) 2(0,0) 3(0.838,0)
JPSLD02
  rect 0.61x1.549 smd: 1(-0.406,0) 2(0.406,0)
L0806_DFE
  rect 0.787x1.803 smd: 1(-0.794,0) 2(0.794,0)
L1008H47
  rect 0.787x2.007 smd: 1(-0.994,0) 2(0.994,0)
L1206-3
  rect 1.6x1.803 smd: 1(-1.397,0) 2(1.397,0)
LED0603-2
  rect 0.787x0.787 smd: A(0.787,0) C(-0.787,0)
LSMSQ118H47_WE
  rect 1.295x3.404 smd: 1(-1.048,0) 2(1.048,0)
LSMSQ157H83
  rect 1.473x3.683 smd: 1(-1.232,0) 2(1.232,0)
LSMSQ260H118
  rect 2.946x3.505 smd: 1(-2.723,0) 2(2.723,0)
LSMSQ272H157
  rect 2.692x2.21 smd: 1(-2.546,0) 2(2.546,0)
M12401598E4_2A
  round 0.787 hole 0.66 unplated: (-3.6,4.34)
  oval 1.067x0.787 hole 0.94x0.66 unplated: (3.6,4.34)
  rect 0.305x0.711 smd: A1(-2.75,5) A2(-2.25,5) A3(-1.75,5) A4(-1.25,5) A5(-0.75,5) A6(-0.25,5) A7(0.25,5) A8(0.75,5) A9(1.25,5) A10(1.75,5) A11(2.25,5) A12(2.75,5) B1(2.5,3.3) B2(2,3.3) B3(1.5,3.3) B4(1,3.3) B5(0.5,3.3) B6(0,3.3) B7(-0.5,3.3) B8(-1,3.3) B9(-1.5,3.3) B10(-2,3.3) B11(-2.5,3.3) B12(-3,3.3)
  oval 0.813x1.397 hole 0.508x1.118: SH1(-4.13,3.09) SH2(4.13,3.09) SH3(-4.49,-2.86) SH4(4.49,-2.86)
MSOP8_PAD1_88X1_68
  rect 0.457x1.448 smd: 1(-0.975,-2.2) 2(-0.325,-2.2) 3(0.325,-2.2) 4(0.975,-2.2) 5(0.975,2.2) 6(0.325,2.2) 7(-0.325,2.2) 8(-0.975,2.2)
  rect 1.88x1.676 smd: PAD(0,0)
QFN16_3X3_PAD1_1X1_1
  oval 0.305x0.889 smd: 1(-0.75,-1.5) 2(-0.25,-1.5) 3(0.25,-1.5) 4(0.75,-1.5) 9(0.75,1.5) 10(0.25,1.5) 11(-0.25,1.5) 12(-0.75,1.5)
  oval 0.889x0.305 smd: 5(1.5,-0.75) 6(1.5,-0.25) 7(1.5,0.25) 8(1.5,0.75) 13(-1.5,0.75) 14(-1.5,0.25) 15(-1.5,-0.25) 16(-1.5,-0.75)
  rect 1.092x1.092 smd: PAD(0,0)
R0402
  rect 0.635x0.737 smd: 1(-0.5,0) 2(0.5,0)
R0402H26
  rect 0.508x0.508 smd: 1(-0.496,0) 2(0.496,0)
R0603
  rect 0.787x0.991 smd: 1(-0.85,0) 2(0.85,0)
R0603H35
  rect 0.813x0.813 smd: 1(-0.907,0) 2(0.907,0)
R0805
  rect 1.041x1.397 smd: 1(-0.95,0) 2(0.95,0)
SC70
  rect 0.406x0.508 smd: 1(-0.65,-0.95) 2(0,-0.95) 3(0.65,-0.95) 4(0.65,0.95) 5(0,0.95) 6(-0.65,0.95)
SO8
  rect 0.61x2.184 smd: 1(-1.905,-2.54) 2(-0.635,-2.54) 3(0.635,-2.54) 4(1.905,-2.54) 5(1.905,2.54) 6(0.635,2.54) 7(-0.635,2.54) 8(-1.905,2.54)
SOD323
  rect 1.27x0.889 smd: A(1.143,0) C(-1.143,0)
SOD323F
  rect 0.838x0.457 smd: A(1.14,0) C(-1.14,0)
SOT23
  rect 1.016x1.397 smd: 1(-0.94,-1.118) 2(0.94,-1.118) 3(0,1.118)
SWPANASONIC_EVQ
  rect 3.2x0.991 smd: 1(-3.4,-2) 2(3.4,-2) 3(-3.4,2) 4(3.4,2)
SWSML236W138H205
  rect 2.794x2.159 smd: 1(-2.412,0) 2(2.412,0)
TDFN14_PAD2_3X1_7
  rect 0.229x0.559 smd: 1(-1.2,-1.469) 2(-0.8,-1.469) 3(-0.4,-1.469) 4(0,-1.469) 5(0.4,-1.469) 6(0.8,-1.469) 7(1.2,-1.469) 8(1.2,1.469) 9(0.8,1.469) 10(0.4,1.469) 11(0,1.469) 12(-0.4,1.469) 13(-0.8,1.469) 14(-1.2,1.469)
  rect 2.311x1.702 smd: PAD(0,0)
TPSMC40
  round 1.016 smd: 1(0,0)
unnamed#2
  round 4.445 hole 3.175 unplated: (0,0)
WLCSP30H27
  round 0.254 smd: A1(-1,-1.25) A2(-1,-0.75) A3(-1,-0.25) A4(-1,0.25) A5(-1,0.75) A6(-1,1.25) B1(-0.5,-1.25) B2(-0.5,-0.75) B3(-0.5,-0.25) B4(-0.5,0.25) B5(-0.5,0.75) B6(-0.5,1.25) C1(0,-1.25) C2(0,-0.75) C3(0,-0.25) C4(0,0.25) C5(0,0.75) C6(0,1.25) D1(0.5,-1.25) D2(0.5,-0.75) D3(0.5,-0.25) D4(0.5,0.25) D5(0.5,0.75) D6(0.5,1.25) E1(1,-1.25) E2(1,-0.75) E3(1,-0.25) E4(1,0.25) E5(1,0.75) E6(1,1.25)
WLCSP35H27
  round 0.229 smd: A1(-0.8,-1.2) A2(-0.8,-0.8) A3(-0.8,-0.4) A4(-0.8,0) A5(-0.8,0.4) A6(-0.8,0.8) A7(-0.8,1.2) B1(-0.4,-1.2) B2(-0.4,-0.8) B3(-0.4,-0.4) B4(-0.4,0) B5(-0.4,0.4) B6(-0.4,0.8) B7(-0.4,1.2) C1(0,-1.2) C2(0,-0.8) C3(0,-0.4) C4(0,0) C5(0,0.4) C6(0,0.8) C7(0,1.2) D1(0.4,-1.2) D2(0.4,-0.8) D3(0.4,-0.4) D4(0.4,0) D5(0.4,0.4) D6(0.4,0.8) D7(0.4,1.2) E1(0.8,-1.2) E2(0.8,-0.8) E3(0.8,-0.4) E4(0.8,0) E5(0.8,0.4) E6(0.8,0.8) E7(0.8,1.2)
WLCSP60H27
  round 0.229 smd: A1(-1,-1.8) A2(-1,-1.4) A3(-1,-1) A4(-1,-0.6) A5(-1,-0.2) A6(-1,0.2) A7(-1,0.6) A8(-1,1) A9(-1,1.4) A10(-1,1.8) B1(-0.6,-1.8) B2(-0.6,-1.4) B3(-0.6,-1) B4(-0.6,-0.6) B5(-0.6,-0.2) B6(-0.6,0.2) B7(-0.6,0.6) B8(-0.6,1) B9(-0.6,1.4) B10(-0.6,1.8) C1(-0.2,-1.8) C2(-0.2,-1.4) C3(-0.2,-1) C4(-0.2,-0.6) C5(-0.2,-0.2) C6(-0.2,0.2) C7(-0.2,0.6) C8(-0.2,1) C9(-0.2,1.4) C10(-0.2,1.8) D1(0.2,-1.8) D2(0.2,-1.4) D3(0.2,-1) D4(0.2,-0.6) D5(0.2,-0.2) D6(0.2,0.2) D7(0.2,0.6) D8(0.2,1) D9(0.2,1.4) D10(0.2,1.8) E1(0.6,-1.8) E2(0.6,-1.4) E3(0.6,-1) E4(0.6,-0.6) E5(0.6,-0.2) E6(0.6,0.2) E7(0.6,0.6) E8(0.6,1) E9(0.6,1.4) E10(0.6,1.8) F1(1,-1.8) F2(1,-1.4) F3(1,-1) F4(1,-0.6) F5(1,-0.2) F6(1,0.2) F7(1,0.6) F8(1,1) F9(1,1.4) F10(1,1.8)
WLP30_21-0762
  round 0.229 smd: A1(-1,0.8) A2(-0.6,0.8) A3(-0.2,0.8) A4(0.2,0.8) A5(0.6,0.8) A6(1,0.8) B1(-1,0.4) B2(-0.6,0.4) B3(-0.2,0.4) B4(0.2,0.4) B5(0.6,0.4) B6(1,0.4) C1(-1,0) C2(-0.6,0) C3(-0.2,0) C4(0.2,0) C5(0.6,0) C6(1,0) D1(-1,-0.4) D2(-0.6,-0.4) D3(-0.2,-0.4) D4(0.2,-0.4) D5(0.6,-0.4) D6(1,-0.4) E1(-1,-0.8) E2(-0.6,-0.8) E3(-0.2,-0.8) E4(0.2,-0.8) E5(0.6,-0.8) E6(1,-0.8)
WLP49_2_958X2_958
  round 0.229 smd: A1(-1.2,1.2) A2(-0.8,1.2) A3(-0.4,1.2) A4(0,1.2) A5(0.4,1.2) A6(0.8,1.2) A7(1.2,1.2) B1(-1.2,0.8) B2(-0.8,0.8) B3(-0.4,0.8) B4(0,0.8) B5(0.4,0.8) B6(0.8,0.8) B7(1.2,0.8) C1(-1.2,0.4) C2(-0.8,0.4) C3(-0.4,0.4) C4(0,0.4) C5(0.4,0.4) C6(0.8,0.4) C7(1.2,0.4) D1(-1.2,0) D2(-0.8,0) D3(-0.4,0) D4(0,0) D5(0.4,0) D6(0.8,0) D7(1.2,0) E1(-1.2,-0.4) E2(-0.8,-0.4) E3(-0.4,-0.4) E4(0,-0.4) E5(0.4,-0.4) E6(0.8,-0.4) E7(1.2,-0.4) F1(-1.2,-0.8) F2(-0.8,-0.8) F3(-0.4,-0.8) F4(0,-0.8) F5(0.4,-0.8) F6(0.8,-0.8) F7(1.2,-0.8) G1(-1.2,-1.2) G2(-0.8,-1.2) G3(-0.4,-1.2) G4(0,-1.2) G5(0.4,-1.2) G6(0.8,-1.2) G7(1.2,-1.2)

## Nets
0V9: C52.1 C56.1 C60.1 C64.1 C68.1 C72.1 L6.2(N2) OUT4.1(N1) R43.1
1V2: C51.1 C55.1 C59.1 C63.1 C67.1 C71.1 L5.2(N2) OUT3.1(N1) R41.1
1V8: C50.1 C54.1 C58.1 C62.1 C66.1 C70.1 L4.2(N2) OUT2.1(N1) R40.1
1V8_VIO: C101.1 C107.1 C108.1 C109.1 L8.2(N2) P10.2(N2) P11.1 P22.1 P23.1 P24.1 P26.1 P27.1 P29.1 R88.1 R89.1 R102.1 U13.3 U13.10(VL) UNK1V8_VIO.1
3V3: C49.1 C53.1 C57.1 C61.1 C65.1 C69.1 L3.2(N2) OUT1.1(N1) R38.1
5V0: C24.1 C27.1 OUT5.1(N1) P3.1 P4.2(N2) P14.14 R82.2(N2) U3.D4 U3.E4 U3.E5 U3.E6
5V0_VIO: C114.1 P21.1 P50.1 U10.1 UNK5V0_VIO.1
12V0: C3.1 P1.3 P1.4(N4) U1.A4 U1.A5 U1.B5 U1.C5 U1.D5 UNK12V0.1
AGND: C1.1 C2.2(N2) C3.2(N2) C4.2(N2) C5.2(N2) C6.2(N2) C7.2(N2) C8.2(N2) C9.2(N2) C10.2(N2) C11.2(N2) C13.2(N2) C14.2(N2) C15.2(N2) C16.2(N2) C18.2(N2) C19.2(N2) C22.2(N2) C23.2(N2) C24.2(N2) C25.2(N2) C26.2(N2) C27.2(N2) C28.2(N2) C29.2(N2) C30.2(N2) C31.2(N2) C32.2(N2) C33.2(N2) C34.2(N2) C35.2(N2) C36.2(N2) C37.2(N2) C38.2(N2) C43.2(N2) C46.2(N2) C48.2(N2) C49.2(N2) C50.2(N2) C51.2(N2) C52.2(N2) C53.2(N2) C54.2(N2) C55.2(N2) C56.2(N2) C57.2(N2) C58.2(N2) C59.2(N2) C60.2(N2) C61.2(N2) C62.2(N2) C63.2(N2) C64.2(N2) C65.2(N2) C66.2(N2) C67.2(N2) C68.2(N2) C69.2(N2) C70.2(N2) C71.2(N2) C72.2(N2) C73.N(N2) C74.2(N2) C75.2(N2) C76.2(N2) C78.2(N2) C79.2(N2) C80.2(N2) C81.2(N2) C83.2(N2) C84.2(N2) C85.2(N2) C86.2(N2) C88.2(N2) C89.2(N2) C90.2(N2) C91.2(N2) C92.2(N2) C93.2(N2) C94.2(N2) C95.2(N2) C97.2(N2) C98.2(N2) C101.2(N2) C102.2(N2) C103.2(N2) C104.2(N2) C105.2(N2) C106.2(N2) C108.2(N2) C109.2(N2) C114.2(N2) C116.2(N2) CSN.1(N1) D2.A(P) D3.A(P) D4.A(P) E1.2(N2) GND1.1(N1) GND2.1(N1) GND3.1(N1) GND4.1(N1) GND5.1(N1) GND6.1(N1) GNDC.1(N1) M1.A1 M1.A12 M1.B1 M1.B12 OUT-.1(N1) P1.1 P1.2 P9.1 P14.3 P14.5 P14.7 P14.8 P14.9(N9) P14.11 P14.12 P14.13 P14.15 P14.16 P15.6 P28.2(N2) P38.2(N2) P39.3(N3) P42.1 P47.3(N3) R1.2(N2) R2.2(N2) R6.1 R7.1 R11.2(N2) R12.2(N2) R20.2(N2) R32.2(N2) R33.2(N2) R39.1 R42.1 R45.2(N2) R46.2(N2) R48.2(N2) R49.1 R50.2(N2) R53.2(N2) R54.1 R55.2(N2) R57.2(N2) R62.2(N2) R72.2(N2) R77.2(N2) R79.2(N2) R81.2(N2) R84.2(N2) R98.2(N2) R101.2(N2) R110.2(N2) R112.2(N2) R117.2(N2) RT1.2(N2) TP19.1(N1) U1.B3 U1.B4 U1.C4 U1.E4 U2.C5 U2.D4 U2.D6 U3.C3 U3.C4 U3.C5 U3.C6 U3.C7 U3.D2 U3.D3 U3.E2 U4.6 U5.15 U5.16 U5.PAD U6.A1 U6.A2 U6.A9 U6.A10 U6.C6 U6.F1 U6.F2 U6.F6 U6.F9 U6.F10 U7.2 U8.C5 U8.C6 U8.F1 U8.F2 U8.F3 U8.G1 U8.G2 U9.8 U9.PAD U10.3 U13.7 U13.PAD U14.4
PVDD: C23.1 C104.1 P11.3(N3) U8.G3
VBUS: C2.1 C4.1 M1.A4 M1.A9 M1.B4(VBUS_4) M1.B9 P13.1 U1.A2 U1.A3 U1.B2 U1.C2 U1.D2 U2.A6 VBUS.1(N1)
VCC_EXT: C102.1 P15.2 P44.1 P49.1 U13.14 VCC_EXT.1(N1)
VDD: C38.1 U6.F5
VIN_U14: C116.1 P10.1 P47.1 R61.1 R109.1 R111.1 R115.1 R116.1 U14.8
AVL: C11.1 U2.C6
BATSP: P20.2 U8.D7
BATT: C22.1 C26.1 C77.2(N2) C82.1 P20.1 P40.1 R65.1 R67.1 R87.1 S2.2(B) U8.E6 U8.F6 U8.F7 U8.G6 U8.G7
BATT_N: C40.2(N2) C41.2(N2) CSP.1(N1) D1.1(P) P2.2(N2) R31.1 R33.1 U4.5 U4.PAD U8.E7
BATT_P: D1.3 P2.1 P20.3(N3) P43.1 P48.1 R30.1 R44.2(N2) TP30.1(N1)
CC1: M1.A5 U2.A3
CC2: M1.B5 U2.A4
CE: P3.2(N2) U6.A7
CHGIN: C14.1 P30.1 U8.A1 U8.A2 U8.B1 U8.B2
DIS: Q2.4 R36.2(N2) TP32.1(N1)
DN: R16.2(N2) U2.D1
DN1: U2.E1
DN_USBC: M1.A7 M1.B7 R16.1 R90.1 R94.2(N2)
DP: R17.2(N2) U2.D2
DP2: U2.E2
DP_USBC: M1.A6 M1.B6 R17.1 R26.1 R93.2(N2)
IN+: C87.2(N2) IN+.1(N1) P14.4 P14.10 R83.2(N2) R84.1 U3.E1
INAOK_N: R9.1 U1.E1 U7.3
INBOK_N: R10.1 U1.E6 U7.1
LX2: C21.2(N2) L1.1 U3.D5 U3.D6 U3.D7 U3.E7
OUT+: C87.1 OUT+.1(N1) P14.2 P14.6 R82.1 R83.1
PCKP: C48.1 D2.C P40.3(N3) R67.2(N2) U4.11
PP_VOUT: C7.1 P30.2(N2) P45.1 PP_OUT.1(N1) U1.A1 U1.A6 U1.B1 U1.B6 U1.C1 U1.C6 U1.D1 U1.D6
QBEXT: P16.2 U8.A5
REG: C41.1 P27.3(N3) U4.7
S1: P40.2 R66.2(N2)
SCL: C94.1 D4.C R22.2(N2) R25.2(N2) R37.1 R56.2(N2) R78.2(N2) R79.1 R88.2(N2) R113.2(N2) R115.2(N2) SCL.1(N1) TP31.1(N1) U2.B2 U3.A1 U6.A4 U8.A3 U13.2
SCL_EXT: P15.8 SCL_EXT.1(N1) U13.12
SDA: C93.1 D3.C R21.2(N2) R58.2(N2) R59.1 R80.2(N2) R81.1 R86.1 R89.2(N2) R114.2(N2) R116.2(N2) SDA.1(N1) TP20.1(N1) U2.B3 U3.B1 U6.A5 U8.B3 U13.1
SDA_EXT: P15.4 SDA_EXT.1(N1) U13.13
SNS1N: R39.2(N2) U6.E5
SNS1P: R38.2(N2) U6.E4
SNS2P: R40.2(N2) U6.B4
SNS3N: R42.2(N2) U6.B6
SNS3P: R41.2(N2) U6.B7
SNS4P: R43.2(N2) U6.E7
THM: C16.1 JP1.2(COM) U8.B5
U6_IN: C33.1 C34.1 C35.1 C36.1 C37.1 P4.1 R68.2(N2) R73.2(N2) R74.2(N2) R75.2(N2) U6.E6
U9_IN: C89.1 C90.1 P12.1 P39.1 P43.2(N2) P44.2(N2) P45.2(N2) U9.2(VIN)
UNNAMED_2_ADMAX147XX_I1_ENN: P5.2(N2) R6.2(N2) U1.D4
UNNAMED_2_ADMAX147XX_I1_OTGEB: P8.1 R12.1 U1.E5
UNNAMED_2_ADMAX147XX_I1_OTGENA: P7.1 R11.1 U1.E2
UNNAMED_2_ADMAX147XX_I1_OVLOA: R1.1 U1.C3
UNNAMED_2_ADMAX147XX_I1_OVLOB: R2.1 U1.D3
UNNAMED_2_ADMAX147XX_I1_PCON: P6.2(N2) R7.2(N2) U1.E3(PCON)
UNNAMED_2_ADMAX173XXV2_I188_ALRT: R34.1 U4.10
UNNAMED_2_ADMAX173XXV2_I188_BATT: C39.2(N2) C40.1 R30.2(N2) U4.3
UNNAMED_2_ADMAX173XXV2_I188_CHG: R35.1 TP6.1(N1) U4.14
UNNAMED_2_ADMAX173XXV2_I188_CP: C39.1 U4.2
UNNAMED_2_ADMAX173XXV2_I188_DIS: R36.1 U4.12
UNNAMED_2_ADMAX173XXV2_I188_PFAIL: R32.1 U4.4
UNNAMED_2_ADMAX173XXV2_I188_SCL: R37.2(N2) U4.9
UNNAMED_2_ADMAX173XXV2_I188_SDA: R86.2(N2) U4.8
UNNAMED_2_ADMAX173XXV2_I188_TH: R31.2(N2) U4.1
UNNAMED_2_ADMAX173XXV2_I188_ZVC: P9.2(N2) U4.13(ZVC)
UNNAMED_2_ADMAX7778X_I78_BST: C20.1 U8.C3
UNNAMED_2_ADMAX7778X_I78_BYP1: C25.1 C28.1 C29.1 U8.C1 U8.C2
UNNAMED_2_ADMAX7778X_I78_DISQBAT: P36.1 U8.D5
UNNAMED_2_ADMAX7778X_I78_DN: R94.1 U8.B7
UNNAMED_2_ADMAX7778X_I78_DN1: R90.2(N2) U8.A7
UNNAMED_2_ADMAX7778X_I78_DP: R93.1 U8.B6
UNNAMED_2_ADMAX7778X_I78_DP1: R26.2(N2) U8.A6
UNNAMED_2_ADMAX7778X_I78_ENBST: R24.1 U8.C4
UNNAMED_2_ADMAX7778X_I78_EXTSM: R23.2(N2) U8.D6
UNNAMED_2_ADMAX7778X_I78_IRQB: R28.2(N2) U8.B4
UNNAMED_2_ADMAX7778X_I78_LX1: C20.2(N2) L2.1 U8.D1 U8.D2 U8.D3 U8.E1 U8.E2 U8.E3
UNNAMED_2_ADMAX7778X_I78_STAT: P37.1 U8.E4
UNNAMED_2_ADMAX7778X_I78_SUSPND: P25.1 U8.D4
UNNAMED_2_ADMAX7778X_I78_VDD: C19.1 U8.C7
UNNAMED_2_ADMAX7778X_I78_VIO: P11.2 U8.A4(VIO)
UNNAMED_2_CAP_I62_N1: C10.1 U2.A2
UNNAMED_2_CAP_I65_N1: C9.1 U2.B5
UNNAMED_2_CAP_I217_N1: C79.1 P32.2(N2)
UNNAMED_2_CAP_I222_N1: C78.1 P31.2(N2)
UNNAMED_2_CAP_I224_N1: C80.1 P33.2(N2)
UNNAMED_2_CAP_I227_N1: C81.1 P34.2(N2)
UNNAMED_2_CAP_I232_N2: C12.2(N2) C77.1
UNNAMED_2_CAP_I235_N2: C82.2(N2) C83.1
UNNAMED_2_CN2P_I163_N2: C103.1 P13.2(N2) U2.B6
UNNAMED_2_CN3P_I312_N1: P16.1 R64.2(N2)
UNNAMED_2_CN3P_I312_N3: P16.3(N3) R65.2(N2)
UNNAMED_2_DIOLED_I24_N: DS1.C U7.6
UNNAMED_2_DIOLED_I24_P: DS1.A(P) R18.2(N2)
UNNAMED_2_DIOLED_I25_N: DS2.C U7.4(Y2)
UNNAMED_2_DIOLED_I25_P: DS2.A(P) R19.2(N2)
UNNAMED_2_DIOLED_I282_N: DS3.C P37.2(N2)
UNNAMED_2_DIOLED_I282_P: DS3.A(P) R29.2(N2)
UNNAMED_2_ICMAX77958_I12_GPIO0: TP1.1(N1) U2.E6
UNNAMED_2_ICMAX77958_I12_GPIO1: TP9.1(N1) U2.B4
UNNAMED_2_ICMAX77958_I12_GPIO2: TP10.1(N1) U2.E5
UNNAMED_2_ICMAX77958_I12_GPIO03: TP11.1(N1) U2.D5
UNNAMED_2_ICMAX77958_I12_GPIO4: TP12.1(N1) U2.E4
UNNAMED_2_ICMAX77958_I12_GPIO5: TP13.1(N1) U2.E3
UNNAMED_2_ICMAX77958_I12_GPIO7: TP17.1(N1) U2.D3
UNNAMED_2_ICMAX77958_I12_GPIO8: TP18.1(N1) U2.C4
UNNAMED_2_ICMAX77958_I12_INTB: R63.1 U2.A1
UNNAMED_2_ICMAX77958_I12_SCLM: R8.2(N2) U2.C2
UNNAMED_2_ICMAX77958_I12_SDAM: R5.2(N2) U2.C3
UNNAMED_2_MODUSB24P4PSHLD_I13_SH1: C1.2(N2) E1.1 M1.SH1 M1.SH2 M1.SH3 M1.SH4
UNNAMED_2_NC2P_I36_N2: P7.2(N2) R13.1
UNNAMED_2_NC2P_I42_N2: P8.2(N2) R14.1
UNNAMED_2_NC2P_I46_N1: P5.1 R3.2(N2)
UNNAMED_2_NC2P_I48_N1: P6.1 R4.2(N2)
UNNAMED_2_NC3PJMPR_I301_A: JP1.1 RT1.1
UNNAMED_2_NC3PJMPR_I301_B: JP1.3 R20.1
UNNAMED_2_RES_I183_N2: Q1.4 R35.2(N2)
UNNAMED_2_RES_I185_N1: C12.1 Q1.1 Q1.2 Q1.3(S3) R44.1 S1.2
UNNAMED_2_RES_I234_N1: R66.1 S1.4(N4)
UNNAMED_2_RES_I264_N2: Q2.1 Q2.2 Q2.3(S3) R87.2(N2)
UNNAMED_2_RES_I295_N1: R23.1 S2.1
UNNAMED_2_TRANNMOSFETV15_I187_D1: Q1.5 Q1.6 Q1.7 Q1.8 Q2.5 Q2.6 Q2.7 Q2.8
UNNAMED_3_ADMAX77542_I19_ALTIN: ALT_IN.1(N1) C32.1 U6.D6
UNNAMED_3_ADMAX77542_I19_BST1: C42.1 U6.F3
UNNAMED_3_ADMAX77542_I19_BST2: C44.1 U6.A3
UNNAMED_3_ADMAX77542_I19_BST3: C45.1 U6.A8
UNNAMED_3_ADMAX77542_I19_BST4: C47.1 U6.F8
UNNAMED_3_ADMAX77542_I19_IN11: R68.1 U6.D1 U6.D2
UNNAMED_3_ADMAX77542_I19_IN21: R73.1 U6.C1 U6.C2
UNNAMED_3_ADMAX77542_I19_IN31: R74.1 U6.C9 U6.C10
UNNAMED_3_ADMAX77542_I19_IN41: R75.1 U6.D9 U6.D10
UNNAMED_3_ADMAX77542_I19_LX11: C42.2(N2) L3.1 U6.E1 U6.E2
UNNAMED_3_ADMAX77542_I19_LX21: C44.2(N2) L4.1 U6.B1 U6.B2
UNNAMED_3_ADMAX77542_I19_LX31: C45.2(N2) L5.1 U6.B9 U6.B10
UNNAMED_3_ADMAX77542_I19_LX41: C47.2(N2) L6.1 U6.E9 U6.E10
UNNAMED_3_ADMAX77542_I19_VL12: C46.1 U6.F4
UNNAMED_3_ADMAX77542_I19_VL34: C43.1 U6.F7(VL34)
UNNAMED_3_ADMAX77542_I31_CFG1: R54.2(N2) U6.C5
UNNAMED_3_ADMAX77542_I31_CFG2: R49.2(N2) U6.D5
UNNAMED_3_ADMAX77542_I31_IRQB: R60.1 U6.B5
UNNAMED_3_ADMAX77542_I31_MFIO1: R15.1 U6.E3
UNNAMED_3_ADMAX77542_I31_MFIO2: TP23.1(N1) U6.D3
UNNAMED_3_ADMAX77542_I31_MFIO3: R47.1 U6.C3
UNNAMED_3_ADMAX77542_I31_MFIO4: TP25.1(N1) U6.B3
UNNAMED_3_ADMAX77542_I31_MFIO5: R70.1 U6.B8
UNNAMED_3_ADMAX77542_I31_MFIO6: TP27.1(N1) U6.C8
UNNAMED_3_ADMAX77542_I31_MFIO7: R85.1 U6.D8
UNNAMED_3_ADMAX77542_I31_MFIO8: TP29.1(N1) U6.E8
UNNAMED_3_ADMAX77542_I31_SEL1: R46.1 U6.D4
UNNAMED_3_ADMAX77542_I31_SEL2: R48.1 U6.C4
UNNAMED_3_ADMAX77542_I31_SEL3: R50.1 U6.C7
UNNAMED_3_ADMAX77542_I31_SEL4: R55.1 U6.D7
